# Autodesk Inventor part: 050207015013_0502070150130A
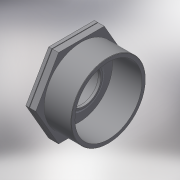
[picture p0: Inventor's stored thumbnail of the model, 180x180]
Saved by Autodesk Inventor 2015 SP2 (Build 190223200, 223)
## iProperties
Created: 2017-05
Part Number: 050207015013_0502070150130A
Material: Generic
Description: PLASSON REDUCING BUSHING 1.1/2"-1.1/4"
Document SubType Name: Modeling
Designer: KIM
Density: 1 g/cm^3
Appearance: Default
Author: KIM
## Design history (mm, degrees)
derived "050207.ipt"
feature "Solid1::050207.ipt"
tag "TaggingFeature1"
body "Solid1"
other parameters: "d1" = 47.803, "d5" = 21, "d8" = 0.37, "d12" = 0, "d15" = 37, "d19" = 0, "d30" = 9.25, "d31" = 4.625, "d33" = 38.952, "d34" = 43.0227, "d36" = 2.5, "d37" = 41.67864, "d38" = 24.42, "d39" = 35.0568, "d40" = 2.1, "d41" = 0, "H_" = 37, "R_" = 47.803, "l_2" = 21, "Rp_" = 38.952
